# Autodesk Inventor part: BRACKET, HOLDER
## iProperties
Title: BRACKET, HOLDER
Author: J. DESIGNER
Revision Number: A
Shininess: 50.0
PropertySet Name: _Private Model Information
Created: 2000-11
Part Number: B106
Project: ACME
User Status: ECO 20001
Description: HOLDER, BRACKET
Document SubType Name: Modeling
Designer: E. MOSS
Control State: 0
Master: False
Checked Out: False
PropertySet Name: Design Tracking Control
Density: 0.0
Volumn: 0.0
Area: 0.0
PropertySet Name: Model Information
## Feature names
1. Revolution1
2. Extrusion1
3. Extrusion2
4. Extrusion3
5. Extrusion4
6. Extrusion5
7. Extrusion6
8. Fillet1
9. Extrusion7
10. LARGE THRU HOLES [Hole]
11. Hole2
12. Hole3
13. Hole4
14. Extrusion8
15. Hole5
16. Hole6
17. Hole7
18. Hole8
19. Fillet2
20. Fillet3
21. Fillet4
22. Fillet5
23. Fillet6
